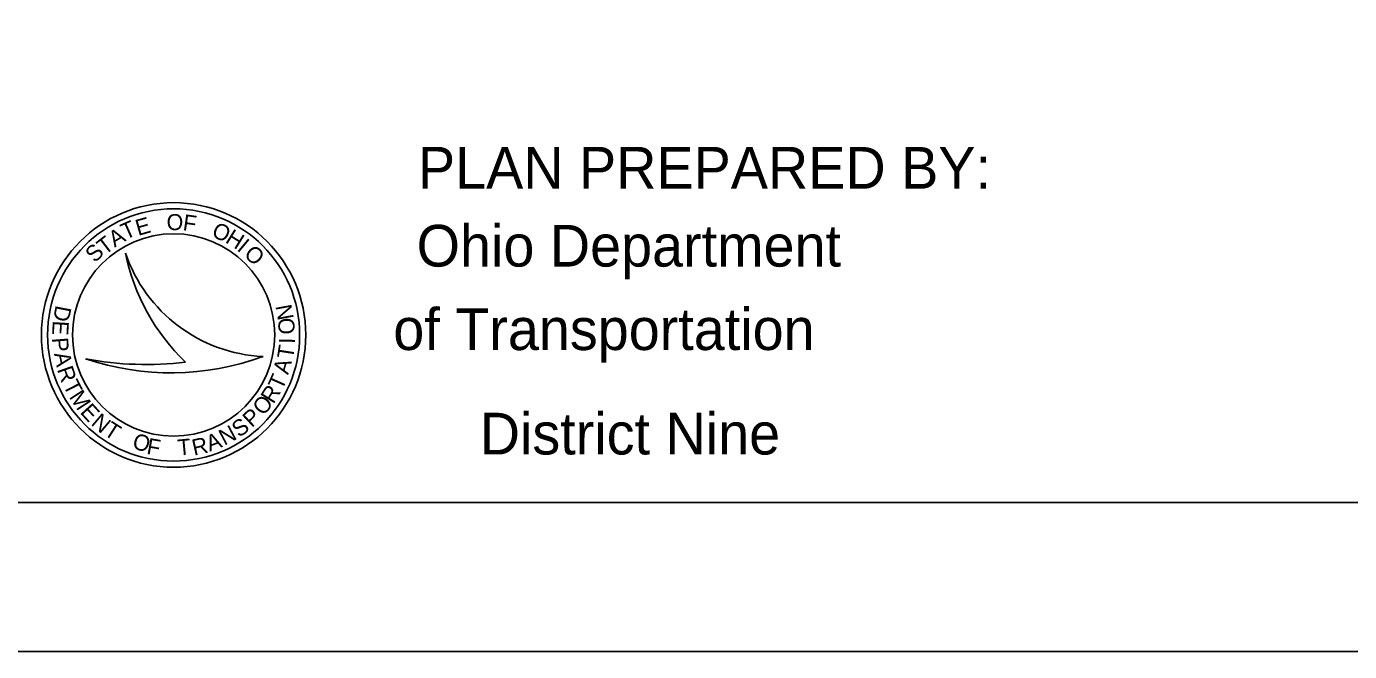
# Model space of a CAD drawing. Extents: x 0 to 34, y -7.5 to 22.
# Drawn here: x 2.298 to 6.742, y 0 to 2.097 of the extents above; entities that cross this region are included whole.
import ezdxf

# ---------------------------------------------------------------- set-up
doc = ezdxf.new("R2010")
doc.units = 0
for name, color, linetype in [('SH_Border', 7, 'Continuous'), ('SH_Cut_Line', 7, 'Continuous'), ('SH_Data', 7, 'Continuous'), ('SH_Text', 7, 'Continuous')]:
    doc.layers.add(name, color=color, linetype=linetype)

msp = doc.modelspace()

# ---------------------------------------------------------------- linework, layer by layer
at = {"layer": 'SH_Border'}
msp.add_lwpolyline([(1.5, 21.5), (33.5, 21.5), (33.5, 0.5), (1.5, 0.5)], close=True, dxfattribs=at)
at = {"layer": 'SH_Cut_Line'}
msp.add_lwpolyline([(0, 0), (34, 0), (34, 22), (0, 22)], close=True, dxfattribs=at)
at = {"layer": 'SH_Data'}
for p in [(3.0907, 0.9861), (3.0907, 0.9927)]:
    msp.add_line(p, (3.0907, 0.9927), dxfattribs=at)
for radius in [0.4439, 0.4233, 0.3394]:
    msp.add_circle((2.7919, 1.0622), radius, dxfattribs=at)
for centre, radius, start, end in [((3.1169, 1.504), 0.5148, 198.9257, 267.1657), ((3.3217, 1.4796), 0.7064, 191.6379, 226.0963), ((2.7825, 1.8347), 0.8995, 251.4527, 290.0832), ((2.7014, 2.0871), 1.1241, 259.4964, 276.6689)]:
    msp.add_arc(centre, radius, start, end, dxfattribs=at)

# ---------------------------------------------------------------- texts
for s, height, rotation, p in [('O', 0.0539, 359.9091, (2.7682, 1.414)), ('F', 0.0541, 351.9674, (2.8208, 1.414)), ('T', 0.0541, 23.9678, (2.6299, 1.3811)), ('E', 0.0541, 16.043, (2.6727, 1.3942)), ('O', 0.0539, 335.793, (2.9162, 1.3942)), ('T', 0.0541, 37.6476, (2.5608, 1.3284)), ('A', 0.0541, 31.1261, (2.5937, 1.3547)), ('H', 0.0541, 327.9389, (2.9623, 1.3745)), ('I', 0.0541, 320.2199, (3.0018, 1.3481)), ('S', 0.0541, 45.4775, (2.5279, 1.3021)), ('O', 0.0541, 318.5022, (3.0248, 1.3284)), ('D', 0.0539, 259.12, (2.3963, 1.1639)), ('N', 0.0539, 100.5286, (3.196, 1.1178)), ('O', 0.0541, 92.9555, (3.1993, 1.0651)), ('E', 0.0541, 266.6484, (2.3864, 1.1112)), ('P', 0.0541, 274.2753, (2.3831, 1.052)), ('T', 0.0541, 81.2026, (3.1927, 0.9796)), ('I', 0.0541, 88.6028, (3.1993, 1.0322)), ('A', 0.0541, 281.7405, (2.3897, 0.9993)), ('R', 0.0539, 289.4003, (2.3996, 0.9467)), ('T', 0.0541, 66.0112, (3.1565, 0.8742)), ('A', 0.0541, 73.5293, (3.1762, 0.9269)), ('T', 0.0541, 296.9819, (2.4193, 0.894)), ('R', 0.0541, 58.3738, (3.1269, 0.8282)), ('M', 0.0541, 303.081, (2.4391, 0.8545)), ('O', 0.0541, 50.7234, (3.094, 0.7887)), ('E', 0.0541, 312.2703, (2.4753, 0.8018)), ('P', 0.0539, 43.1954, (3.0545, 0.7492)), ('N', 0.0541, 319.7501, (2.5115, 0.7624)), ('T', 0.0541, 327.4174, (2.5542, 0.7294)), ('N', 0.0541, 28.0344, (2.9623, 0.69)), ('S', 0.0541, 35.6162, (3.0117, 0.7163)), ('O', 0.0541, 342.6135, (2.6497, 0.6834)), ('F', 0.0541, 350.1546, (2.699, 0.6636)), ('T', 0.0541, 5.2461, (2.8076, 0.657)), ('R', 0.0541, 12.9016, (2.8603, 0.657)), ('A', 0.0541, 20.3744, (2.913, 0.6702))]:
    msp.add_text(s, height=height, rotation=rotation, dxfattribs=at).set_placement(p)
for s, p in [('Ohio Department ', (3.6081, 1.2916)), ('of Transportation', (3.5297, 1.0116)), ('District Nine', (3.8201, 0.6611))]:
    msp.add_text(s, height=0.14, dxfattribs=at).set_placement(p)
at = {"layer": 'SH_Text'}
msp.add_text('PLAN PREPARED BY:', height=0.14, dxfattribs=at).set_placement((3.6125, 1.553))

doc.saveas('drawing.dxf')
